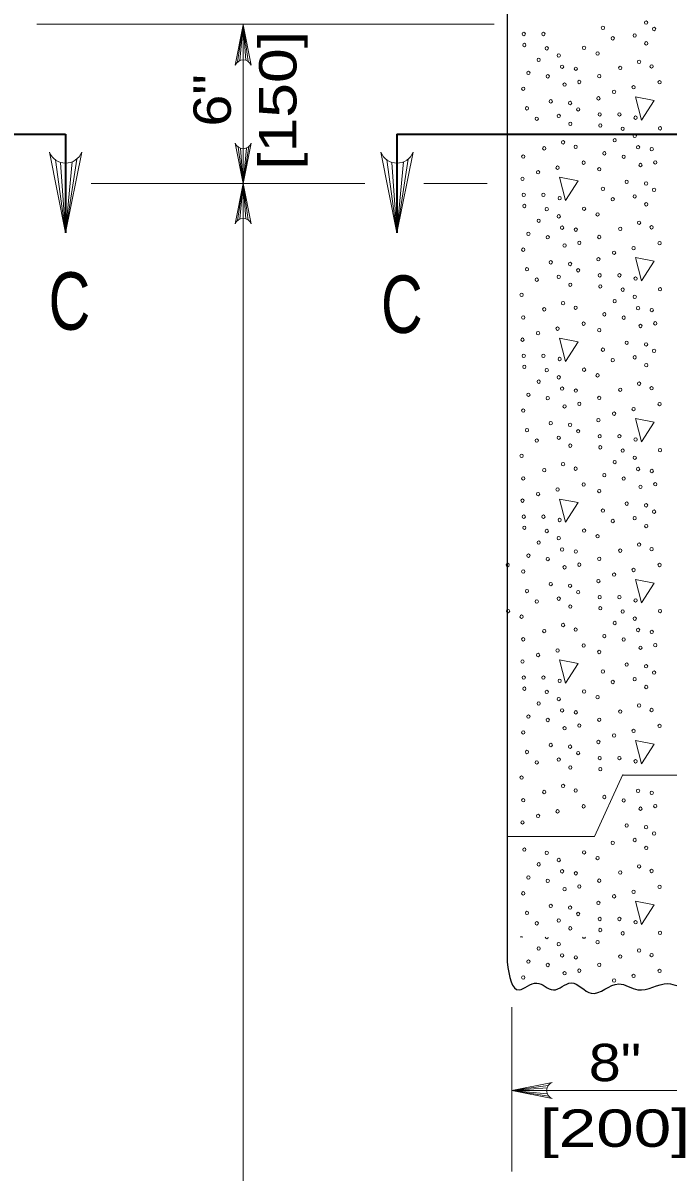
# Model space of a CAD drawing. Extents: x 1083.1 to 1117.1, y 697.4 to 719.4.
# Drawn here: x 1091.892 to 1094.585, y 710.538 to 715.339 of the extents above; entities that cross this region are included whole.
import ezdxf
from ezdxf.enums import TextEntityAlignment as Align

# ---------------------------------------------------------------- set-up
doc = ezdxf.new("R2010")
doc.units = 0
doc.header["$LTSCALE"] = 0.062
doc.linetypes.add('LONG_DASHED', pattern=[7.5, 6, -1.5])
doc.layers.add('1', color=7, linetype='Continuous', lineweight=13)

msp = doc.modelspace()

# ---------------------------------------------------------------- linework, layer by layer
at = {"layer": '1'}
for p, q in [((1091.949, 715.33333), (1093.8595, 715.33333)), ((1092.78792, 715.17625), (1092.8115, 715.33033)), ((1092.79783, 715.18208), (1092.8115, 715.33033)), ((1092.8115, 715.18475), (1092.8115, 715.33033)), ((1092.82225, 715.18317), (1092.8115, 715.33033)), ((1092.83283, 715.178), (1092.8115, 715.33033)), ((1092.79017, 714.82067), (1092.8115, 714.66842)), ((1092.80067, 714.8155), (1092.8115, 714.66842)), ((1092.835, 714.8225), (1092.8115, 714.66842)), ((1092.82517, 714.81667), (1092.8115, 714.66842)), ((1092.8115, 714.814), (1092.8115, 714.66842)), ((1092.02717, 714.76733), (1092.06975, 714.46275)), ((1092.04825, 714.757), (1092.06975, 714.46275)), ((1092.11683, 714.77092), (1092.06975, 714.46275)), ((1092.09708, 714.75925), (1092.06975, 714.46275)), ((1092.06975, 714.75392), (1092.06975, 714.46275)), ((1093.411, 714.76733), (1093.45367, 714.46275)), ((1093.43208, 714.757), (1093.45367, 714.46275)), ((1093.50075, 714.77092), (1093.45367, 714.46275)), ((1093.481, 714.75925), (1093.45367, 714.46275)), ((1093.45367, 714.75392), (1093.45367, 714.46275)), ((1092.06975, 714.72117), (1092.06975, 714.51567)), ((1092.17658, 714.66842), (1093.31908, 714.66842)), ((1092.78792, 714.51433), (1092.8115, 714.66842)), ((1092.79783, 714.52017), (1092.8115, 714.66842)), ((1092.8115, 714.52292), (1092.8115, 714.66842)), ((1092.82225, 714.52133), (1092.8115, 714.66842)), ((1092.83275, 714.51617), (1092.8115, 714.66842)), ((1093.56633, 714.66842), (1093.83058, 714.66842)), ((1092.8115, 707.72683), (1092.8115, 711.52217)), ((1093.93308, 711.23125), (1093.93308, 710.54458)), ((1094.08542, 710.90408), (1093.93308, 710.88275)), ((1094.08025, 710.8935), (1093.93308, 710.88275)), ((1094.55308, 710.88275), (1093.93308, 710.88275)), ((1094.07867, 710.88275), (1093.93308, 710.88275)), ((1094.08133, 710.86908), (1093.93308, 710.88275)), ((1094.08717, 710.85917), (1093.93308, 710.88275)), ((1094.811, 710.88275), (1094.55308, 710.88275))]:
    msp.add_line(p, q, dxfattribs=at)
at = {"layer": '1', "lineweight": 35}
for p, q in [((1086.01117, 714.874), (1092.06975, 714.874)), ((1092.06975, 714.874), (1092.06975, 714.46275)), ((1093.45367, 714.874), (1100.04975, 714.874)), ((1093.45367, 714.874), (1093.45367, 714.46275))]:
    msp.add_line(p, q, dxfattribs=at)
at = {"layer": '1', "linetype": 'LONG_DASHED'}
for p, q in [((1094.39633, 712.20125), (1094.27833, 711.94283)), ((1094.39633, 712.19967), (1099.02808, 712.19967)), ((1093.91808, 711.94283), (1094.27833, 711.94283))]:
    msp.add_line(p, q, dxfattribs=at)
at = {"layer": '1', "lineweight": 25}
msp.add_lwpolyline([(1093.91333, 715.848), (1093.91333, 711.52217), (1093.91333, 711.41925)], dxfattribs=at)
at = {"layer": '1'}
for points in [[(1092.77783, 715.16208), (1092.8115, 715.33033), (1092.84517, 715.16208)], [(1092.8115, 714.689), (1092.8115, 714.9435), (1092.8115, 715.33033)], [(1092.137, 714.79917), (1092.06975, 714.46275), (1092.00242, 714.79917)], [(1092.84508, 714.83658), (1092.8115, 714.66842), (1092.77783, 714.83658)], [(1093.52092, 714.79917), (1093.45367, 714.46275), (1093.38633, 714.79917)], [(1092.77783, 714.50025), (1092.8115, 714.66842), (1092.84508, 714.50025)], [(1092.8115, 711.52217), (1092.8115, 714.66842), (1092.8115, 714.689)], [(1094.10133, 710.84908), (1093.93308, 710.88275), (1094.10133, 710.91642)]]:
    msp.add_lwpolyline(points, dxfattribs=at)
for points in [[(1094.44925, 715.03083), (1094.47483, 714.9335), (1094.52708, 715.01567)], [(1094.132, 714.695), (1094.15767, 714.59775), (1094.20992, 714.67992)], [(1094.44925, 714.35925), (1094.47483, 714.26183), (1094.52708, 714.344)], [(1094.132, 714.02342), (1094.15767, 713.926), (1094.20992, 714.00825)], [(1094.44925, 713.68758), (1094.47483, 713.59025), (1094.52708, 713.67242)], [(1094.132, 713.35175), (1094.15767, 713.25442), (1094.20992, 713.33658)], [(1094.44925, 713.01592), (1094.47483, 712.91858), (1094.52708, 713.00075)], [(1094.132, 712.68008), (1094.15767, 712.58275), (1094.20992, 712.66492)], [(1094.44925, 712.34425), (1094.47483, 712.24692), (1094.52708, 712.32908)], [(1094.44925, 711.67267), (1094.47483, 711.57525), (1094.52708, 711.65742)]]:
    msp.add_lwpolyline(points, close=True, dxfattribs=at)
for centre, radius, start, end in [((1092.81152, 715.14849), 0.03631, 22.08782, 157.91395), ((1092.06967, 714.82638), 0.07261, 202.08782, 337.91395), ((1092.81143, 714.85021), 0.03631, 202.08782, 337.91395), ((1093.45357, 714.82638), 0.07261, 202.08782, 337.91395), ((1092.81152, 714.48664), 0.03631, 22.08782, 157.91395), ((1094.11489, 710.88278), 0.03631, 112.08782, 247.91395)]:
    msp.add_arc(centre, radius, start, end, dxfattribs=at)
for centre in [(1094.31364, 715.31827), (1094.49381, 715.34033), (1094.52749, 715.31374), (1093.98301, 715.29286), (1094.06527, 715.29286), (1094.35477, 715.27473), (1094.44639, 715.28654), (1093.98555, 715.24663), (1094.07897, 715.23303), (1094.23482, 715.23482), (1094.49466, 715.25357), (1094.0455, 715.18495), (1094.12945, 715.20309), (1094.29133, 715.21126), (1094.46468, 715.1765), (1094.00241, 715.13027), (1094.1432, 715.15596), (1094.20056, 715.14773), (1094.38586, 715.15115), (1094.51692, 715.15747), (1094.0832, 715.11605), (1094.1534, 715.08157), (1094.2151, 715.09249), (1094.2982, 715.11689), (1094.55027, 715.09126), (1093.981, 715.06406), (1094.29509, 715.02415), (1094.36011, 715.05135), (1094.44153, 715.07038), (1093.99644, 714.98245), (1094.09578, 715.0115), (1094.17661, 715.0045), (1094.21029, 714.97792), (1094.03757, 714.9389), (1094.12919, 714.95071), (1094.30021, 714.95704), (1094.38247, 714.95704), (1094.45009, 714.94344), (1094.17746, 714.91775), (1094.30275, 714.91081), (1094.39617, 714.89721), (1094.55202, 714.899), (1094.14748, 714.84068), (1094.3627, 714.84913), (1094.44665, 714.86726), (1094.06866, 714.81532), (1094.19971, 714.82165), (1094.31962, 714.79444), (1094.4604, 714.82013), (1094.51776, 714.81191), (1093.981, 714.78107), (1094.23307, 714.75543), (1094.4004, 714.78023), (1094.4706, 714.74575), (1094.5323, 714.75666), (1093.97788, 714.68832), (1094.04291, 714.71553), (1094.12433, 714.73456), (1094.2982, 714.72823), (1094.31364, 714.64663), (1094.41298, 714.67567), (1094.49381, 714.66868), (1094.52749, 714.64209), (1093.98301, 714.62121), (1094.06527, 714.62121), (1094.13289, 714.60761), (1094.35477, 714.60308), (1094.44639, 714.61489), (1093.98555, 714.57498), (1094.07897, 714.56138), (1094.23482, 714.56317), (1094.49466, 714.58192), (1094.0455, 714.5133), (1094.12945, 714.53144), (1094.29133, 714.53961), (1094.46468, 714.50485), (1094.00241, 714.45862), (1094.1432, 714.48431), (1094.20056, 714.47608), (1094.38586, 714.4795), (1094.51692, 714.48582), (1094.0832, 714.4444), (1094.1534, 714.40992), (1094.2151, 714.42084), (1094.2982, 714.44524), (1094.55027, 714.41961), (1093.981, 714.39241), (1094.29509, 714.3525), (1094.36011, 714.3797), (1094.44153, 714.39873), (1093.99644, 714.3108), (1094.09578, 714.33985), (1094.17661, 714.33285), (1094.21029, 714.30627), (1094.03757, 714.26726), (1094.12919, 714.27907), (1094.30021, 714.28539), (1094.38247, 714.28539), (1094.45009, 714.27179), (1094.17746, 714.2461), (1094.30275, 714.23916), (1094.39617, 714.22556), (1094.55202, 714.22735), (1093.97413, 714.20378), (1094.14748, 714.16903), (1094.3627, 714.17748), (1094.44665, 714.19561), (1094.06866, 714.14367), (1094.19971, 714.15), (1094.31962, 714.12279), (1094.4604, 714.14849), (1094.51776, 714.14026), (1093.981, 714.10942), (1094.23307, 714.08378), (1094.4004, 714.10858), (1094.4706, 714.0741), (1094.5323, 714.08501), (1093.97788, 714.01667), (1094.04291, 714.04388), (1094.12433, 714.06291), (1094.2982, 714.05658), (1094.31364, 713.97498), (1094.41298, 714.00402), (1094.49381, 713.99703), (1094.52749, 713.97044), (1093.98301, 713.94957), (1094.06527, 713.94957), (1094.13289, 713.93596), (1094.35477, 713.93143), (1094.44639, 713.94324), (1093.98555, 713.90333), (1094.07897, 713.88973), (1094.23482, 713.89152), (1094.49466, 713.91027), (1094.0455, 713.84165), (1094.12945, 713.85979), (1094.29133, 713.86796), (1094.46468, 713.8332), (1094.00241, 713.78697), (1094.1432, 713.81266), (1094.20056, 713.80443), (1094.38586, 713.80785), (1094.51692, 713.81417), (1094.0832, 713.77275), (1094.1534, 713.73828), (1094.2151, 713.74919), (1094.2982, 713.77359), (1094.55027, 713.74796), (1093.981, 713.72076), (1094.29509, 713.68085), (1094.36011, 713.70805), (1094.44153, 713.72708), (1093.99644, 713.63915), (1094.09578, 713.6682), (1094.17661, 713.6612), (1094.21029, 713.63462), (1094.03757, 713.59561), (1094.12919, 713.60742), (1094.30021, 713.61374), (1094.38247, 713.61374), (1094.45009, 713.60014), (1094.17746, 713.57445), (1094.30275, 713.56751), (1094.39617, 713.55391), (1094.55202, 713.5557), (1093.97413, 713.53214), (1094.14748, 713.49738), (1094.3627, 713.50583), (1094.44665, 713.52396), (1094.06866, 713.47202), (1094.19971, 713.47835), (1094.31962, 713.45115), (1094.4604, 713.47684), (1094.51776, 713.46861), (1093.981, 713.43777), (1094.23307, 713.41213), (1094.4004, 713.43693), (1094.4706, 713.40245), (1094.5323, 713.41337), (1093.97788, 713.34503), (1094.04291, 713.37223), (1094.12433, 713.39126), (1094.2982, 713.38493), (1094.31364, 713.30333), (1094.41298, 713.33238), (1094.49381, 713.32538), (1094.52749, 713.29879), (1093.98301, 713.27792), (1094.06527, 713.27792), (1094.13289, 713.26432), (1094.35477, 713.25978), (1094.44639, 713.27159), (1093.98555, 713.23168), (1094.07897, 713.21808), (1094.23482, 713.21987), (1094.49466, 713.23862), (1094.0455, 713.17), (1094.12945, 713.18814), (1094.29133, 713.19631), (1094.46468, 713.16155), (1094.00241, 713.11532), (1094.1432, 713.14101), (1094.20056, 713.13278), (1094.38586, 713.1362), (1094.51692, 713.14252), (1093.91587, 713.07631), (1094.0832, 713.1011), (1094.1534, 713.06663), (1094.2151, 713.07754), (1094.2982, 713.10194), (1094.55027, 713.07631), (1093.981, 713.04911), (1094.29509, 713.0092), (1094.36011, 713.0364), (1094.44153, 713.05543), (1093.99644, 712.9675), (1094.09578, 712.99655), (1094.17661, 712.98955), (1094.21029, 712.96297), (1094.03757, 712.92396), (1094.12919, 712.93577), (1094.30021, 712.94209), (1094.38247, 712.94209), (1094.45009, 712.92849), (1093.91762, 712.88405), (1094.17746, 712.9028), (1094.30275, 712.89586), (1094.39617, 712.88226), (1094.55202, 712.88405), (1093.97413, 712.86049), (1094.14748, 712.82573), (1094.3627, 712.83418), (1094.44665, 712.85231), (1094.06866, 712.80037), (1094.19971, 712.8067), (1094.31962, 712.7795), (1094.4604, 712.80519), (1094.51776, 712.79696), (1093.981, 712.76612), (1094.23307, 712.74048), (1094.4004, 712.76528), (1094.4706, 712.7308), (1094.5323, 712.74172), (1093.97788, 712.67338), (1094.04291, 712.70058), (1094.12433, 712.71961), (1094.2982, 712.71328), (1094.31364, 712.63168), (1094.41298, 712.66073), (1094.49381, 712.65373), (1094.52749, 712.62714), (1093.98301, 712.60627), (1094.06527, 712.60627), (1094.13289, 712.59267), (1094.35477, 712.58813), (1094.44639, 712.59994), (1093.98555, 712.56004), (1094.07897, 712.54643), (1094.23482, 712.54823), (1094.49466, 712.56698), (1094.0455, 712.49836), (1094.12945, 712.51649), (1094.29133, 712.52466), (1094.46468, 712.4899), (1094.00241, 712.44367), (1094.1432, 712.46936), (1094.20056, 712.46113), (1094.38586, 712.46455), (1094.51692, 712.47087), (1094.0832, 712.42946), (1094.1534, 712.39498), (1094.2151, 712.40589), (1094.2982, 712.4303), (1094.44153, 712.38378), (1094.55027, 712.40466), (1093.981, 712.37746), (1094.29509, 712.33755), (1094.36011, 712.36475), (1093.99644, 712.29585), (1094.09578, 712.3249), (1094.17661, 712.31791), (1094.21029, 712.29132), (1094.03757, 712.25231), (1094.12919, 712.26412), (1094.30021, 712.27044), (1094.38247, 712.27044), (1094.45009, 712.25684), (1094.17746, 712.23115), (1094.30275, 712.22421), (1093.97413, 712.18884), (1094.14748, 712.15408), (1094.06866, 712.12872), (1094.19971, 712.13505), (1094.31962, 712.10785), (1094.4604, 712.13354), (1094.51776, 712.12531), (1093.981, 712.09447), (1094.12433, 712.04796), (1094.23307, 712.06884), (1094.4004, 712.09363), (1094.4706, 712.05915), (1094.5323, 712.07007), (1093.97788, 712.00173), (1094.04291, 712.02893), (1094.41298, 711.98908), (1094.49381, 711.98208), (1094.52749, 711.9555), (1094.35477, 711.91648), (1094.44639, 711.92829), (1093.98555, 711.88839), (1094.07897, 711.87479), (1094.23482, 711.87658), (1094.49466, 711.89533), (1094.0455, 711.82671), (1094.12945, 711.84484), (1094.29133, 711.85301), (1094.46468, 711.81825), (1094.00241, 711.77202), (1094.1432, 711.79771), (1094.20056, 711.78949), (1094.38586, 711.7929), (1094.51692, 711.79922), (1094.0832, 711.75781), (1094.1534, 711.72333), (1094.2151, 711.73424), (1094.2982, 711.75865), (1094.44153, 711.71213), (1094.55027, 711.73301), (1093.981, 711.70581), (1094.29509, 711.6659), (1094.36011, 711.6931), (1093.99644, 711.6242), (1094.09578, 711.65325), (1094.17661, 711.64626), (1094.21029, 711.61967), (1094.03757, 711.58066), (1094.12919, 711.59247), (1094.30021, 711.59879), (1094.38247, 711.59879), (1094.45009, 711.58519), (1094.17746, 711.5595), (1094.30275, 711.55256), (1094.39617, 711.53896), (1094.55202, 711.54075), (1094.0455, 711.47558), (1094.12945, 711.49372), (1094.29133, 711.50189), (1094.1432, 711.44659), (1094.20056, 711.43836), (1094.38586, 711.44178), (1094.46468, 711.46713), (1094.51692, 711.4481), (1094.00241, 711.4209), (1094.0832, 711.40668), (1094.2151, 711.38312), (1094.2982, 711.40752), (1094.55027, 711.38189), (1093.981, 711.35469), (1094.1534, 711.3722), (1094.36011, 711.34198), (1094.44153, 711.36101)]:
    msp.add_ellipse(centre, major_axis=(0, 0.00718), ratio=0.944544, dxfattribs=at)
for centre, start_param, end_param in [((1093.97413, 711.51719), 5.4808807, 7.0854899), ((1094.07897, 711.52366), 1.7785356, 4.5046496), ((1094.23482, 711.52545), 2.0438791, 4.2393062)]:
    msp.add_ellipse(centre, major_axis=(0, 0.00718), ratio=0.944544, start_param=start_param, end_param=end_param, dxfattribs=at)
at = {"layer": '1', "lineweight": 25}
msp.add_spline([(1093.91333, 711.41925), (1093.964, 711.30275), (1094.03767, 711.33133), (1094.10658, 711.3025), (1094.18117, 711.332), (1094.265, 711.2885), (1094.37967, 711.328), (1094.45975, 711.303), (1094.58467, 711.329), (1094.6695, 711.30792), (1094.7835, 711.34008)], degree=3, dxfattribs=at)

# ---------------------------------------------------------------- texts
at = {"layer": '1'}
for s, width, p in [('[150]', 1.25, (1093.03392, 715.01558)), ('6"', 1.15, (1092.75983, 715.01558))]:
    msp.add_text(s, height=0.156, rotation=90, dxfattribs=dict(at, width=width)).set_placement(p, align=Align.CENTER)
at = {"layer": '1', "width": 0.75}
for p in [(1091.99883, 714.05817), (1093.387, 714.04483)]:
    msp.add_text('C', height=0.24, dxfattribs=at).set_placement(p)
at = {"layer": '1'}
for s, width, p in [('8"', 1.15, (1094.364, 710.92175)), ('[200]', 1.35, (1094.364, 710.64767))]:
    msp.add_text(s, height=0.156, dxfattribs=dict(at, width=width)).set_placement(p, align=Align.CENTER)

doc.saveas('drawing.dxf')
